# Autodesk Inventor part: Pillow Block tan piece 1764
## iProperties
Created: 2009-01
Part Number: Pillow Block tan piece 1764
Document SubType Name: Modeling
Designer: lwoods
Density: 1.4 g/cm^3
Material: PVC-Piping
Mass: 9.20302 g
Surface Area: 29.8864 cm^2
Volume: 6.57359 cm^3
Author: lwoods
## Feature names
1. Revolution1
